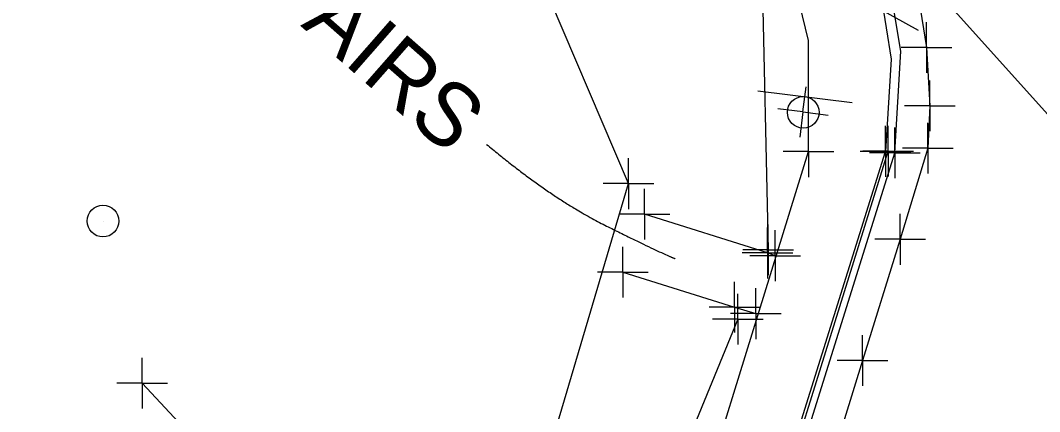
# Model space of a CAD drawing. Extents: x 0 to 1944463, y 0 to 420651.
# Drawn here: x 1943277.4 to 1943357.8, y 417204.7 to 417235.5 of the extents above; entities that cross this region are included whole.
import ezdxf

# ---------------------------------------------------------------- set-up
doc = ezdxf.new("R2010")
doc.units = 0
for name, color, linetype in [('SUR - DTM - Breaklines', 7, 'Continuous'), ('SUR - DTM - Breaklines - Points - Locators', 7, 'Continuous'), ('SUR - DTM - Spot Points - Locators', 7, 'Continuous'), ('SUR - NON-TRAN - Features', 7, 'Continuous'), ('SUR - NON-TRAN - Features - Points - Locators', 7, 'Continuous'), ('SUR - NON-TRAN - Features Text', 7, 'Continuous'), ('SUR - TR-CTRL - Pavement Marking', 7, 'Continuous'), ('SUR - TR-CTRL - Pavement Marking - Points - Locators', 7, 'Continuous'), ('SUR - TR-CTRL - Signs and Devices', 7, 'Continuous'), ('SUR - TR-CTRL - Signs and Devices - Points - Locators', 7, 'Continuous'), ('SUR - TRAN - Features', 7, 'Continuous'), ('SUR - TRAN - Features - Points - Locators', 7, 'Continuous'), ('SUR - UTL - Fiber Optic Cable (Underground)', 7, 'Continuous')]:
    doc.layers.add(name, color=color, linetype=linetype)

msp = doc.modelspace()

# ---------------------------------------------------------------- linework, layer by layer
at = {"layer": 'SUR - DTM - Breaklines'}
for points in [[(1943198.046, 417414.134), (1943214.079, 417390.624), (1943227.284, 417369.761), (1943234.656, 417359.391), (1943251.574, 417339.468), (1943275.895, 417313.326), (1943305.21, 417281.554), (1943319.493, 417266.816), (1943326.151, 417258.389), (1943333.033, 417247.541), (1943335.935, 417239.942), (1943336.414, 417217.406)], [(1943302.769, 417192.969), (1943316.957, 417194.129), (1943325.403, 417222.632), (1943318.173, 417239.593), (1943286.555, 417270.931), (1943267.833, 417289.169), (1943243.263, 417315.732), (1943226.41, 417332.649)], [(1943319.296, 417140.824), (1943327.947, 417167.697), (1943328.56, 417169.574), (1943332.119, 417181.1), (1943332.965, 417183.712), (1943345.886, 417225.185)], [(1943334.036, 417211.955), (1943324.421, 417188.589), (1943318.222, 417187.559), (1943302.047, 417191.774)]]:
    msp.add_lwpolyline(points, dxfattribs=at)
at = {"layer": 'SUR - DTM - Breaklines - Points - Locators'}
for p, q in [((1943345.886, 417225.185), (1943345.886, 417227.185)), ((1943345.886, 417225.185), (1943343.886, 417225.185)), ((1943345.886, 417225.185), (1943347.886, 417225.185)), ((1943345.886, 417225.185), (1943345.886, 417223.185)), ((1943325.403, 417222.632), (1943325.403, 417224.632)), ((1943325.403, 417222.632), (1943323.403, 417222.632)), ((1943325.403, 417222.632), (1943327.403, 417222.632)), ((1943325.403, 417222.632), (1943325.403, 417220.632)), ((1943336.414, 417217.406), (1943336.414, 417219.406)), ((1943336.414, 417217.406), (1943334.414, 417217.406)), ((1943336.414, 417217.406), (1943338.414, 417217.406)), ((1943336.414, 417217.406), (1943336.414, 417215.406)), ((1943334.036, 417211.955), (1943334.036, 417213.955)), ((1943334.036, 417211.955), (1943332.036, 417211.955)), ((1943334.036, 417211.955), (1943336.036, 417211.955)), ((1943334.036, 417211.955), (1943334.036, 417209.955))]:
    msp.add_line(p, q, dxfattribs=at)
at = {"layer": 'SUR - DTM - Spot Points - Locators'}
msp.add_line((1943283.936, 417219.672), (1943283.936, 417219.672), dxfattribs=at)
msp.add_circle((1943283.925, 417219.682), 1.25, dxfattribs=at)
at = {"layer": 'SUR - NON-TRAN - Features'}
for points in [[(1943336.969, 417216.952), (1943336.365, 417217.165), (1943326.669, 417220.228)], [(1943324.962, 417215.646), (1943333.774, 417212.901), (1943335.458, 417212.381)]]:
    msp.add_lwpolyline(points, dxfattribs=at)
at = {"layer": 'SUR - NON-TRAN - Features - Points - Locators'}
for p, q in [((1943326.669, 417220.228), (1943326.669, 417222.228)), ((1943326.669, 417220.228), (1943324.669, 417220.228)), ((1943326.669, 417220.228), (1943328.669, 417220.228)), ((1943326.669, 417220.228), (1943326.669, 417218.228)), ((1943336.365, 417217.165), (1943336.365, 417219.165)), ((1943336.969, 417216.952), (1943336.969, 417218.952)), ((1943324.962, 417215.646), (1943324.962, 417217.646)), ((1943336.365, 417217.165), (1943334.365, 417217.165)), ((1943336.365, 417217.165), (1943338.365, 417217.165)), ((1943336.365, 417217.165), (1943336.365, 417215.165)), ((1943336.969, 417216.952), (1943334.969, 417216.952)), ((1943336.969, 417216.952), (1943338.969, 417216.952)), ((1943336.969, 417216.952), (1943336.969, 417214.952)), ((1943324.962, 417215.646), (1943322.962, 417215.646)), ((1943324.962, 417215.646), (1943326.962, 417215.646)), ((1943324.962, 417215.646), (1943324.962, 417213.646)), ((1943333.774, 417212.901), (1943333.774, 417214.901)), ((1943335.458, 417212.381), (1943335.458, 417214.381)), ((1943333.774, 417212.901), (1943331.774, 417212.901)), ((1943335.458, 417212.381), (1943333.458, 417212.381)), ((1943333.774, 417212.901), (1943335.774, 417212.901)), ((1943333.774, 417212.901), (1943333.774, 417210.901)), ((1943335.458, 417212.381), (1943337.458, 417212.381)), ((1943335.458, 417212.381), (1943335.458, 417210.381))]:
    msp.add_line(p, q, dxfattribs=at)
at = {"layer": 'SUR - NON-TRAN - Features Text'}
msp.add_open_spline([(1943314.203, 417225.732), (1943319.257, 417221.499), (1943327.719, 417217.265), (1943329.089, 417216.711)], degree=2, dxfattribs=at)
at = {"layer": 'SUR - TR-CTRL - Pavement Marking'}
msp.add_lwpolyline([(1943339.796, 417260.236), (1943342.177, 417255.767), (1943344.638, 417249.827), (1943346.627, 417244.08), (1943348.043, 417238.795), (1943348.926, 417233.366), (1943349.189, 417228.776), (1943349.018, 417225.436), (1943346.838, 417218.243), (1943343.875, 417208.692), (1943340.912, 417199.141), (1943337.949, 417189.59), (1943334.986, 417180.039), (1943332.023, 417170.488), (1943329.06, 417160.937), (1943326.096, 417151.387), (1943325.674, 417150.025)], dxfattribs=at)
at = {"layer": 'SUR - TR-CTRL - Pavement Marking - Points - Locators'}
for p, q in [((1943348.926, 417233.366), (1943348.926, 417235.366)), ((1943348.926, 417233.366), (1943346.926, 417233.366)), ((1943348.926, 417233.366), (1943350.926, 417233.366)), ((1943348.926, 417233.366), (1943348.926, 417231.366)), ((1943349.189, 417228.776), (1943349.189, 417230.776)), ((1943349.189, 417228.776), (1943347.189, 417228.776)), ((1943349.189, 417228.776), (1943351.189, 417228.776)), ((1943349.189, 417228.776), (1943349.189, 417226.776)), ((1943349.018, 417225.436), (1943349.018, 417227.436)), ((1943349.018, 417225.436), (1943347.018, 417225.436)), ((1943349.018, 417225.436), (1943351.018, 417225.436)), ((1943349.018, 417225.436), (1943349.018, 417223.436)), ((1943346.838, 417218.243), (1943346.838, 417220.243)), ((1943346.838, 417218.243), (1943344.838, 417218.243)), ((1943346.838, 417218.243), (1943348.838, 417218.243)), ((1943346.838, 417218.243), (1943346.838, 417216.243)), ((1943343.875, 417208.692), (1943343.875, 417210.692)), ((1943343.875, 417208.692), (1943341.875, 417208.692)), ((1943343.875, 417208.692), (1943345.875, 417208.692)), ((1943343.875, 417208.692), (1943343.875, 417206.692))]:
    msp.add_line(p, q, dxfattribs=at)
at = {"layer": 'SUR - TR-CTRL - Signs and Devices'}
msp.add_line((1943335.597, 417229.954), (1943343.041, 417229.043), dxfattribs=at)
msp.add_circle((1943339.188, 417228.255), 1.25, dxfattribs=at)
at = {"layer": 'SUR - TR-CTRL - Signs and Devices - Points - Locators'}
for q in [(1943339.413, 417230.268), (1943337.185, 417228.526), (1943338.927, 417226.298), (1943341.155, 417228.04)]:
    msp.add_line((1943339.17, 417228.283), q, dxfattribs=at)
at = {"layer": 'SUR - TRAN - Features'}
msp.add_line((1943344.024, 417237.068), (1943348.255, 417234.747), dxfattribs=at)
for points in [[(1943327.194, 417273.746), (1943334.623, 417264.429), (1943341.589, 417251.232), (1943344.542, 417242.362), (1943346.13, 417232.439), (1943345.689, 417225.18)], [(1943346.416, 417225.068), (1943346.887, 417233.072), (1943345.721, 417240.182), (1943344.868, 417243.109)], [(1943339.603, 417225.156), (1943339.603, 417233.912), (1943337.989, 417240.637)], [(1943313.69, 417142.591), (1943322.26, 417169.618), (1943322.75, 417171.122), (1943327.268, 417185.282), (1943339.603, 417225.156)], [(1943319.177, 417140.884), (1943327.757, 417167.732), (1943328.335, 417169.755), (1943331.965, 417181.15), (1943332.727, 417183.77), (1943345.689, 417225.18)], [(1943319.789, 417140.644), (1943328.461, 417167.555), (1943328.943, 417169.228), (1943332.602, 417180.909), (1943333.434, 417183.506), (1943346.416, 417225.068)], [(1943287.027, 417206.905), (1943301.46, 417191.422), (1943324.745, 417181.755)]]:
    msp.add_lwpolyline(points, dxfattribs=at)
at = {"layer": 'SUR - TRAN - Features - Points - Locators'}
for p, q in [((1943339.603, 417225.156), (1943339.603, 417227.156)), ((1943345.689, 417225.18), (1943345.689, 417227.18)), ((1943346.416, 417225.068), (1943346.416, 417227.068)), ((1943339.603, 417225.156), (1943337.603, 417225.156)), ((1943339.603, 417225.156), (1943341.603, 417225.156)), ((1943339.603, 417225.156), (1943339.603, 417223.156)), ((1943345.689, 417225.18), (1943343.689, 417225.18)), ((1943346.416, 417225.068), (1943344.416, 417225.068)), ((1943345.689, 417225.18), (1943347.689, 417225.18)), ((1943345.689, 417225.18), (1943345.689, 417223.18)), ((1943346.416, 417225.068), (1943348.416, 417225.068)), ((1943346.416, 417225.068), (1943346.416, 417223.068)), ((1943287.027, 417206.905), (1943287.027, 417208.905)), ((1943287.027, 417206.905), (1943285.027, 417206.905)), ((1943287.027, 417206.905), (1943289.027, 417206.905)), ((1943287.027, 417206.905), (1943287.027, 417204.905))]:
    msp.add_line(p, q, dxfattribs=at)
at = {"layer": 'SUR - UTL - Fiber Optic Cable (Underground)'}
msp.add_lwpolyline([(1943675.935, 416874.811), (1943301.532, 417291.453), (1943229.017, 417377.593), (1943204.769, 417412.08), (1943079.474, 417545.559), (1943001.447, 417611.824), (1942943.851, 417666.04), (1942875.969, 417717.873), (1942785.445, 417773.544), (1942671.047, 417813.855), (1942647.996, 417834.422), (1942364.461, 417940.541)], dxfattribs=at)

# ---------------------------------------------------------------- texts
at = {"layer": 'SUR - NON-TRAN - Features Text'}
msp.add_text('STAIRS', height=5, rotation=318.74395, dxfattribs=at).set_placement((1943293.052, 417240.731))

doc.saveas('drawing.dxf')
